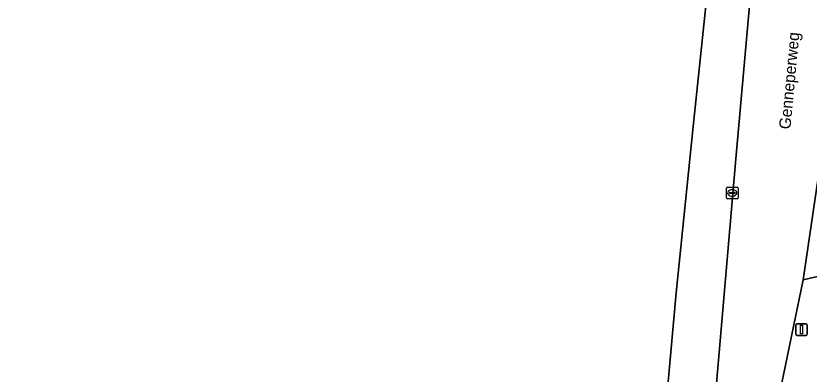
# Model space of a CAD drawing. Extents: x 160203 to 161530, y 379528 to 381797.
# Drawn here: x 160748 to 160816.3, y 380598.1 to 380629 of the extents above; entities that cross this region are included whole.
import ezdxf

# ---------------------------------------------------------------- set-up
doc = ezdxf.new("R2010")
doc.units = 0
for name, color, linetype in [('IMGEO_Berm_groen', 7, 'Continuous'), ('IMGEO_Grasland_agrarisch', 7, 'Continuous'), ('IMGEO_Groenvoorziening', 7, 'Continuous'), ('IMGEO_Hek', 7, 'Continuous'), ('IMGEO_Kolk', 7, 'Continuous'), ('IMGEO_Lichtmast', 7, 'Continuous'), ('IMGEO_Openbare_ruimte_label', 7, 'Continuous'), ('IMGEO_Rijbaan_lokaal_gesloten', 7, 'Continuous'), ('IMGEO_Rijbaan_lokaal_open', 7, 'Continuous')]:
    doc.layers.add(name, color=color, linetype=linetype)

msp = doc.modelspace()

# ---------------------------------------------------------------- linework, layer by layer
at = {"layer": 'IMGEO_Berm_groen'}
msp.add_lwpolyline([(160817.252, 380599.119), (160817.907, 380606.678), (160815.809, 380606.179), (160812.279, 380589.127), (160811.772, 380581.086), (160811.178, 380575.524), (160810.392, 380564.026), (160810.426, 380563.07)], dxfattribs=at)
at = {"layer": 'IMGEO_Grasland_agrarisch'}
msp.add_lwpolyline([(160806.333, 380619.409), (160807.89, 380634.509), (160800.015, 380635.877), (160793.624, 380637.245), (160785.98, 380639.572), (160773.611, 380643.676), (160759.659, 380648.601), (160735.875, 380657.838), (160724.413, 380609.361), (160726.913, 380607.468), (160734.981, 380601.724), (160743.595, 380596.079), (160750.384, 380591.884), (160752.717, 380590.443), (160764.753, 380583.637), (160772.849, 380578.66), (160776.314, 380576.149), (160790.192, 380567.674), (160793.641, 380565.361), (160801.244, 380562.921), (160802.874, 380583.321), (160803.41, 380589.083), (160804.861, 380605.066)], close=True, dxfattribs=at)
at = {"layer": 'IMGEO_Groenvoorziening'}
msp.add_lwpolyline([(160809.998, 380616.634), (160814.161, 380663.374), (160811.37, 380663.358), (160811.078, 380660.23), (160807.89, 380634.509), (160806.333, 380619.409), (160804.861, 380605.066), (160803.41, 380589.083), (160802.874, 380583.321), (160801.244, 380562.921), (160804.651, 380561.649), (160805.988, 380576.064), (160806.416, 380576.035), (160807.06, 380582.557)], close=True, dxfattribs=at)
at = {"layer": 'IMGEO_Hek'}
msp.add_lwpolyline([(160802.874, 380583.321), (160803.41, 380589.083), (160804.861, 380605.066), (160806.333, 380619.409), (160807.89, 380634.509)], dxfattribs=at)
at = {"layer": 'IMGEO_Kolk'}
for p, q in [((160809.191, 380613.254), (160809.191, 380614.106)), ((160809.266, 380614.18), (160810.118, 380614.18)), ((160809.679, 380613.96), (160809.704, 380613.96)), ((160810.192, 380614.106), (160810.192, 380613.254)), ((160810.118, 380613.18), (160809.266, 380613.18)), ((160809.45, 380613.674), (160809.45, 380613.686)), ((160809.888, 380613.637), (160809.49, 380613.637)), ((160809.493, 380613.723), (160809.891, 380613.723)), ((160809.702, 380613.4), (160809.677, 380613.4)), ((160809.934, 380613.686), (160809.934, 380613.674))]:
    msp.add_line(p, q, dxfattribs=at)
for points in [[(160809.191, 380613.254), (160809.191, 380614.106)], [(160809.266, 380614.18), (160810.118, 380614.18)], [(160810.192, 380614.106), (160810.192, 380613.254)], [(160810.118, 380613.18), (160809.266, 380613.18)]]:
    msp.add_lwpolyline(points, dxfattribs=at)
for centre, radius, start, end in [((160809.268, 380614.104), 0.0765, 91.55205, 178.44795), ((160809.268, 380614.104), 0.0765, 91.55205, 178.44795), ((160810.116, 380614.104), 0.0765, 1.55205, 88.44795), ((160810.116, 380614.104), 0.0765, 1.55205, 88.44795), ((160809.268, 380613.256), 0.0765, 181.55205, 268.44795), ((160809.268, 380613.256), 0.0765, 181.55205, 268.44795), ((160809.49, 380613.683), 0.0403, 85.87752, 175.75265), ((160809.487, 380613.673), 0.0366, 178.93798, 274.71019), ((160809.891, 380613.68), 0.043, 264.86636, 352.45326), ((160809.895, 380613.685), 0.0386, 1.73085, 96.63898), ((160810.116, 380613.256), 0.0765, 271.55205, 358.44795), ((160810.116, 380613.256), 0.0765, 271.55205, 358.44795)]:
    msp.add_arc(centre, radius, start, end, dxfattribs=at)
for centre, major_axis, ratio, start_param, end_param in [((160809.678, 380613.68), (-0.387, 0.002), 0.722429, 4.712389, 7.853982), ((160809.703, 380613.68), (-0.39, 0.002), 0.717154, 1.570796, 4.712389)]:
    msp.add_ellipse(centre, major_axis=major_axis, ratio=ratio, start_param=start_param, end_param=end_param, dxfattribs=at)
at = {"layer": 'IMGEO_Lichtmast'}
for p, q in [((160815.162, 380601.499), (160815.162, 380602.299)), ((160815.162, 380602.299), (160815.162, 380601.499)), ((160815.262, 380602.399), (160816.052, 380602.399)), ((160816.052, 380602.399), (160815.262, 380602.399)), ((160816.152, 380602.299), (160816.152, 380601.499)), ((160816.152, 380601.499), (160816.152, 380602.299)), ((160816.052, 380601.399), (160815.262, 380601.399)), ((160815.262, 380601.399), (160816.052, 380601.399))]:
    msp.add_line(p, q, dxfattribs=at)
msp.add_lwpolyline([(160815.582, 380602.274), (160815.732, 380602.274), (160815.732, 380601.524), (160815.582, 380601.524), (160815.582, 380602.274)], dxfattribs=at)
for centre, start, end in [((160815.262, 380602.299), 90, 180), ((160815.262, 380602.299), 90, 180), ((160816.052, 380602.299), 0, 90), ((160816.052, 380602.299), 360, 90), ((160815.262, 380601.499), 180, 270), ((160815.262, 380601.499), 180, 270), ((160816.052, 380601.499), 270, 0), ((160816.052, 380601.499), 270, 0)]:
    msp.add_arc(centre, 0.1, start, end, dxfattribs=at)
at = {"layer": 'IMGEO_Rijbaan_lokaal_gesloten'}
for points in [[(160809.041, 380549.44), (160810.392, 380564.026), (160811.178, 380575.524), (160811.772, 380581.086), (160812.279, 380589.127), (160815.809, 380606.179), (160817.202, 380615.762), (160821.125, 380662.616), (160822.077, 380674.05), (160822.183, 380676.744), (160822.605, 380689.527), (160822.457, 380714.472)], [(160815.749, 380700.692), (160815.747, 380694.014), (160815.747, 380693.241), (160814.474, 380666.576), (160814.161, 380663.374), (160809.998, 380616.634), (160807.06, 380582.557), (160806.416, 380576.035), (160803.96, 380549.663)]]:
    msp.add_lwpolyline(points, dxfattribs=at)
at = {"layer": 'IMGEO_Rijbaan_lokaal_open'}
msp.add_lwpolyline([(160817.202, 380615.762), (160815.809, 380606.179), (160817.907, 380606.678), (160820.598, 380607.319), (160821.655, 380607.516), (160822.663, 380614.174), (160821.198, 380614.513), (160818.686, 380615.298)], close=True, dxfattribs=at)

# ---------------------------------------------------------------- texts
at = {"layer": 'IMGEO_Openbare_ruimte_label'}
msp.add_text('Genneperweg', height=1, rotation=84.66556, dxfattribs=at).set_placement((160814.701, 380619.145))

doc.saveas('drawing.dxf')
